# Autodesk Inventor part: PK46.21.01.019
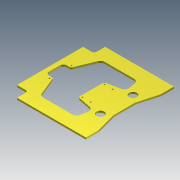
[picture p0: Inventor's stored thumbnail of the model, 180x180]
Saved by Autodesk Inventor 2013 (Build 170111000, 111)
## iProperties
Created: 2005-04
Part Number: PK46.21.01.019
Material: Steel, Mild
Document SubType Name: Modeling
Designer: salex
Manufacturer: Standard
Standards Organization: Custom
Density: 7.86 g/cm^3
Author: salex
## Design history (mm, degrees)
sketch "Эскиз1"
  geometry: L1 (0, 0)-(625, 0); L2 (625, 0)-(625, -120); L3 (625, -120)-(575, -300); L4 (575, -300)-(575, -500); L5 (0, 0)-(0, -100); L6 (0, -100)-(-100, -100); L7 (-100, -100)-(-100, -700); L8 (-60, -450)-(-60, -350); L9 (-30, -320)-(-5, -320); L10 (13.519, -307.552)-(79.848, -144.896); L11 (116.887, -120)-(381.959, -120); L12 (421.24, -152.446)-(432.521, -211.11); L13 (401.187, -257.867)-(290.027, -280.399); L14 (274, -300)-(274, -500); L15 (-32.529, -400)-(706.052, -400); L16 (401.187, -542.133)-(290.027, -519.601); L17 (421.24, -647.554)-(432.521, -588.89); L18 (116.887, -680)-(381.959, -680); L19 (0, -800)-(625, -800); L20 (625, -680)-(575, -500); L21 (0, -800)-(0, -700); L22 (0, -700)-(-100, -700); L23 (-30, -480)-(-5, -480); L24 (13.519, -492.448)-(79.848, -655.104); L25 (625, -800)-(625, -680); C1 r 6.5 at (294, -300); C2 r 6.5 at (294, -500); C3 r 35 at (505, -252); C4 r 35 at (505, -548); C5 r 6.5 at (-5, -300); C6 r 6.5 at (-5, -500); C7 r 6.5 at (368, -300); C8 r 6.5 at (368, -500); A1 r 30 centre (-30, -350) between (-30, -320) and (-60, -350); A2 r 20 centre (-5, -300) between (-5, -320) and (13.519, -307.552); A3 r 20 centre (294, -300) between (290.027, -280.399) and (274, -300); A4 r 40 centre (116.887, -160) between (116.887, -120) and (79.848, -144.896); A5 r 40 centre (381.959, -160) between (421.24, -152.446) and (381.959, -120); A6 r 40 centre (393.241, -218.664) between (401.187, -257.867) and (432.521, -211.11); A7 r 20 centre (294, -500) between (274, -500) and (290.027, -519.601); A8 r 40 centre (393.241, -581.336) between (432.521, -588.89) and (401.187, -542.133); A9 r 40 centre (116.887, -640) between (79.848, -655.104) and (116.887, -680); A10 r 40 centre (381.959, -640) between (381.959, -680) and (421.24, -647.554); A11 r 20 centre (-5, -500) between (13.519, -492.448) and (-5, -480); A12 r 30 centre (-30, -450) between (-60, -450) and (-30, -480); 6 further points
  constraints: 50 end point, 29 symmetric about line, 24 point on circle, 20 centre point, 12 point on line, 12 tangent, 6 equal radius, 6 parallel, 4 perpendicular, 2 coincident, 1 concentric, 1 horizontal, 9 other
  dimensions: "d0" = 725 distance between parallel lines of L2 L7; "d1" = 120 distance of L1.end L2.end; "d2" = 675 distance between parallel lines of L4 L7; "d3" = 300 distance from line of L3.end L1; "d4" = 100 distance of L1.start L5.end; "d5" = 100 distance of L5.end L6.end; "d6" = 325 distance of point (90, -120) point (415, -120); "d7" = 350 horizontal distance of point (440, -250) point (90, -120); "d9" = 800 diameter of L1 L15; "d10" = 560 diameter of L11 L15; "d12" = 20 radius of A2; "d13" = 20 radius of A3; "d15" = 13 diameter of C1 (= d14); "d19" = 130 distance from line of point (440, -250) L11; "d20" = 40 distance between parallel lines of L8 L7; "d23" = 30 radius of A1; "d24" = 40 radius of A4; "d25" = 296 diameter of C3.centre L15; "d26" = 70 diameter of C3; "d27" = 120 distance from line of C3.centre L2; "d32" = 0 horizontal distance of C5.centre C6.centre; "d33" = 299 distance of C1.centre C5.centre; "d35" = 95 distance from line of C6.centre L7; "d36" = 200 distance of C5.centre C6.centre; "d37" = 0 vertical distance of C1.centre C5.centre; "d38" = 200 diameter of C5.centre L15; "d39" = 190 distance from line of point (90, -120) L7; "d40" = 0 vertical distance of C7.centre C5.centre; "d41" = 0 vertical distance of C8.centre C2.centre; "d42" = 0 horizontal distance of C7.centre C8.centre; "d43" = 373 distance of C5.centre C7.centre
extrude "Выдавливание1" new body sketch "Эскиз1" distance "d28" = 16; taper "d29" = 0 deg
fillet "Сопряжение1" dims "d34" = 20
body "Solid1"
other parameters: "d14" = 13
